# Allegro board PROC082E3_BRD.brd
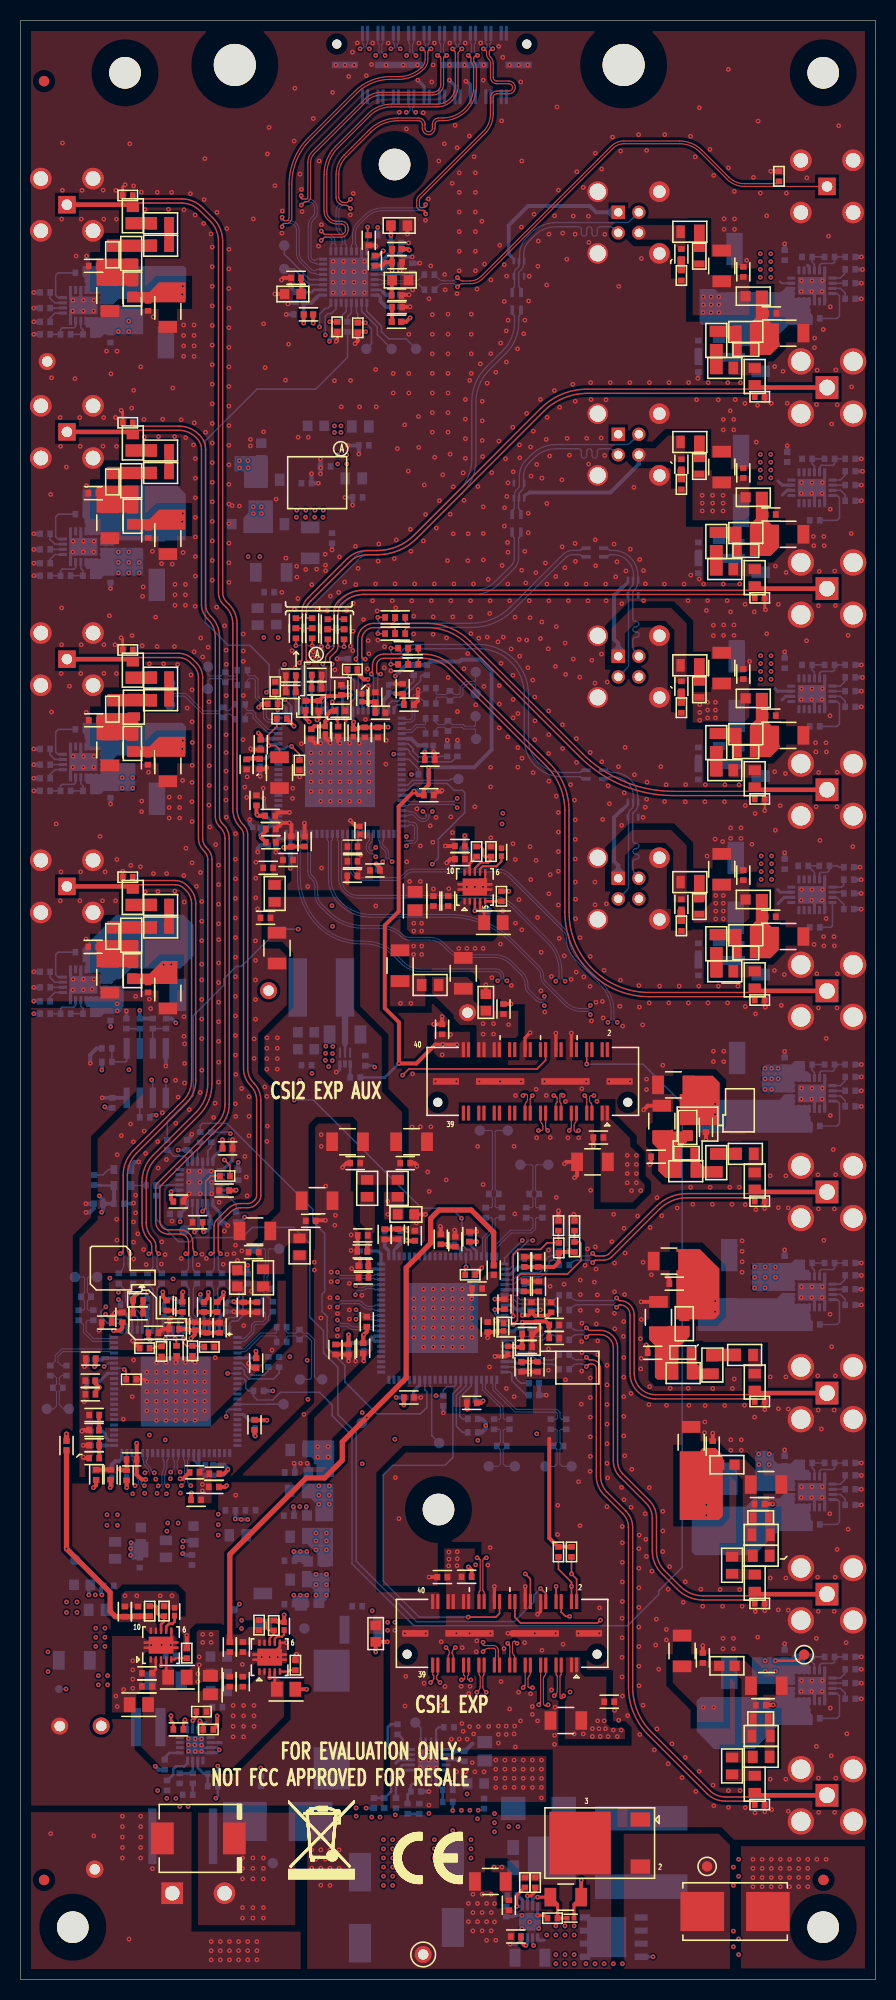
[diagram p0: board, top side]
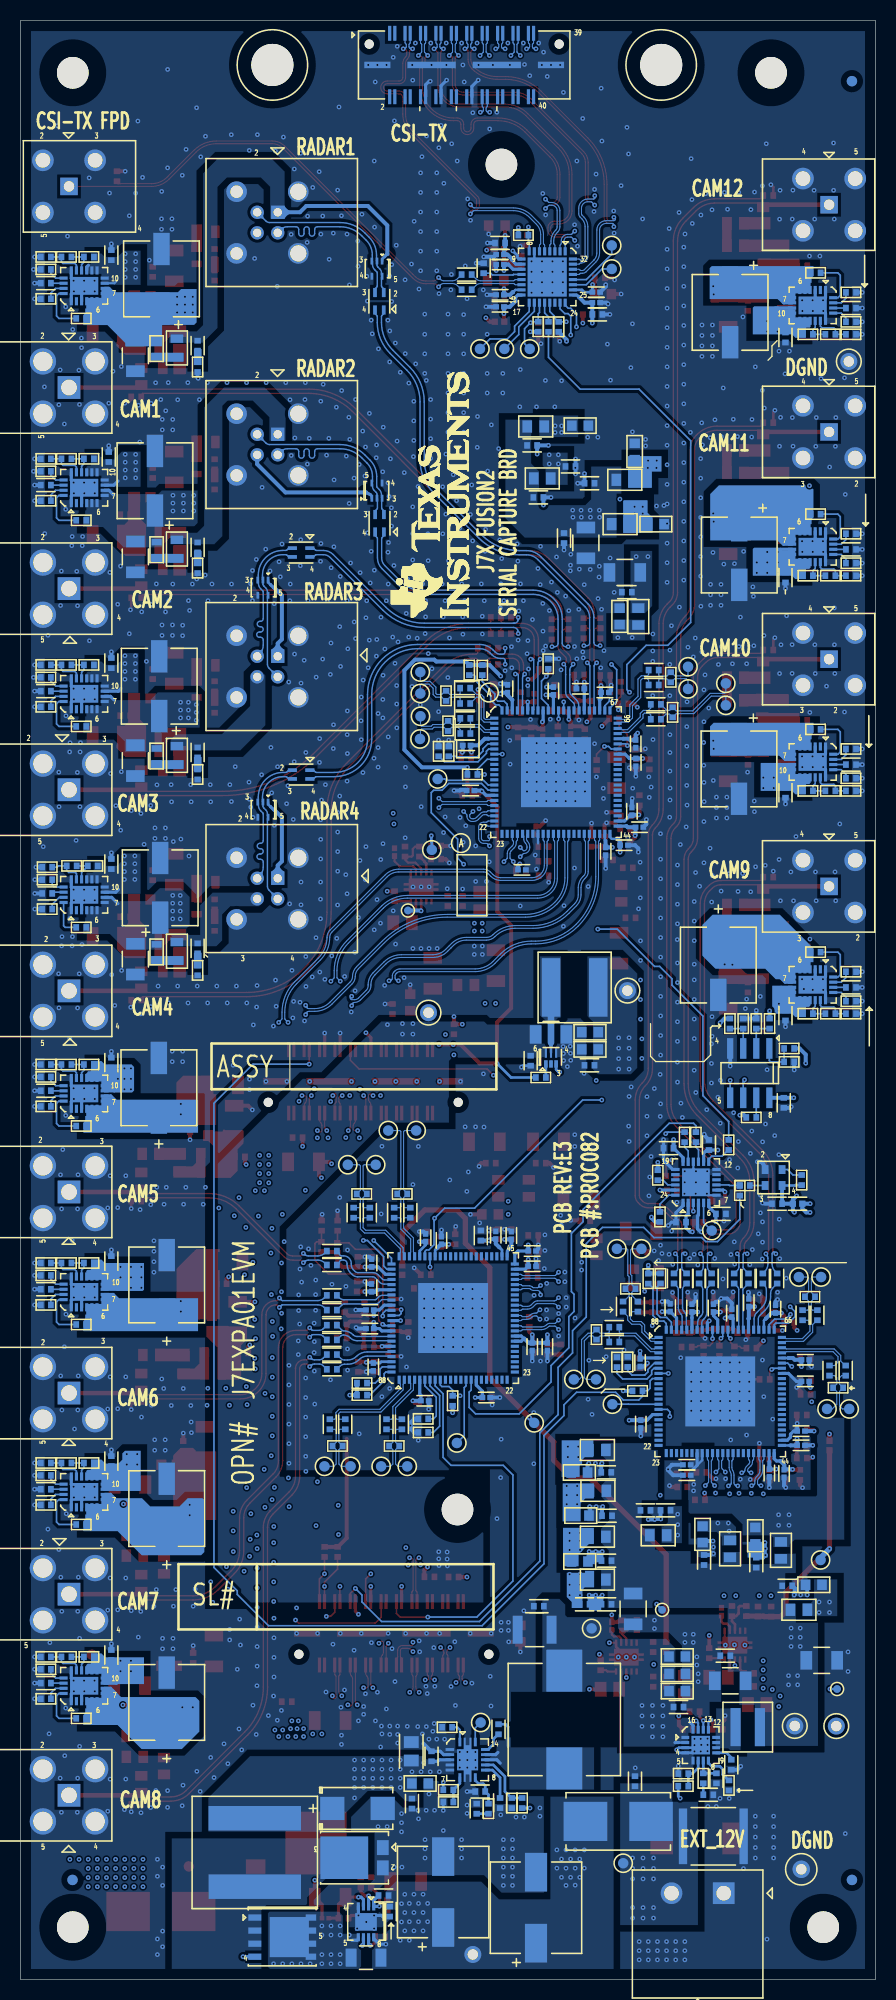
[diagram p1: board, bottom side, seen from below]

Outline 83.16 x 190.5 mm; copper layers: TOP, L02_GND1, L03_SIG1, L04_PWR1, L5_GND2, L6_SIG2, L7_GND3, BOTTOM. Coordinates in mm from the lower left corner of the outline.
Outline path: 0,190.5 0,0 83.16,0 83.16,190.5 0,190.5

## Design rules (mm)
net group C_DOUT_: nets C_DOUT_N C_DOUT_P
net group CAM5_RIN0_: nets CAM5_RIN0_N CAM5_RIN0_P
net group CAM6_RIN1_: nets CAM6_RIN1_N CAM6_RIN1_P
net group CAM7_RIN2_: nets CAM7_RIN2_N CAM7_RIN2_P
net group CAM8_RIN3: nets CAM8_RIN3_N CAM8_RIN3_P
net group CAM9_RIN0_: nets CAM9_RIN0_N CAM9_RIN0_P
net group CAM10_RIN1_: nets CAM10_RIN1_N CAM10_RIN1_P
net group CAM11_RIN2_: nets CAM11_RIN2_N CAM11_RIN2_P
net group CAM12_RIN3_: nets CAM12_RIN3_N CAM12_RIN3_P
net group CMLOUT: nets C_HUB1_CMLOUT3N C_HUB1_CMLOUT3P
net group CMLOUT2: nets C_HUB1_CMLOUT2N C_HUB1_CMLOUT2P
net group DOUT_: nets DOUT_N DOUT_P
net group DP1: nets HUB3_CMLOUT1N HUB3_CMLOUT1P
net group DP2: nets HUB3_CMLOUT0N HUB3_CMLOUT0P
net group DP3: nets HUB3_CMLOUT3N HUB3_CMLOUT3P
net group DP4: nets HUB2_CMLOUT0N HUB2_CMLOUT0P
net group DP_C_HUB3_CMLOUT2: nets C_HUB3_CMLOUT2N C_HUB3_CMLOUT2P
net group DP_CMLOUT0: nets C_HUB1_CMLOUT0N C_HUB1_CMLOUT0P
net group DP_CMLOUT1: nets C_HUB1_CMLOUT1N C_HUB1_CMLOUT1P
net group DP_HUB2_CMLOUT1: nets HUB2_CMLOUT1N HUB2_CMLOUT1P
net group DP_HUB2_CMLOUT2: nets HUB2_CMLOUT2N HUB2_CMLOUT2P
net group DP_HUB2_CMLOUT3: nets HUB2_CMLOUT3N HUB2_CMLOUT3P
net group HUB1_CMLOUT0: nets HUB1_CMLOUT0N HUB1_CMLOUT0P
net group HUB1_CMLOUT1: nets HUB1_CMLOUT1N HUB1_CMLOUT1P
net group HUB1_CMLOUT2: nets HUB1_CMLOUT2N HUB1_CMLOUT2P
net group HUB1_CMLOUT3: nets HUB1_CMLOUT3N HUB1_CMLOUT3P
net group HUB1_RIN0_: nets HUB1_RIN0_N HUB1_RIN0_P
net group HUB1_RIN1_: nets HUB1_RIN1_N HUB1_RIN1_P
net group HUB1_RIN2_: nets HUB1_RIN2_N HUB1_RIN2_P
net group HUB1_RIN3_: nets HUB1_RIN3_N HUB1_RIN3_P
net group HUB2_CMLOUT0: nets C_HUB2_CMLOUT0N C_HUB2_CMLOUT0P
net group HUB2_CMLOUT1: nets C_HUB2_CMLOUT1N C_HUB2_CMLOUT1P
net group HUB2_CMLOUT2: nets C_HUB2_CMLOUT2N C_HUB2_CMLOUT2P
net group HUB2_CMLOUT3: nets C_HUB2_CMLOUT3N C_HUB2_CMLOUT3P
net group HUB3_CMLOUT0: nets C_HUB3_CMLOUT0N C_HUB3_CMLOUT0P
net group HUB3_CMLOUT1: nets C_HUB3_CMLOUT1N C_HUB3_CMLOUT1P
net group HUB3_CMLOUT2: nets HUB3_CMLOUT2N HUB3_CMLOUT2P
net group HUB3_CMLOUT3: nets C_HUB3_CMLOUT3N C_HUB3_CMLOUT3P
net group RDR1_RIN_: nets RDR1_RIN_N RDR1_RIN_P
net group RDR2_RIN_: nets RDR2_RIN_N RDR2_RIN_P
net group RDR3_RIN_: nets RDR3_RIN_N RDR3_RIN_P
net group RDR4_RIN_: nets RDR4_RIN_N RDR4_RIN_P
net group T_RDR1_RIN_: nets T_RDR1_RIN_N T_RDR1_RIN_P
net group T_RDR2_RIN_: nets T_RDR2_RIN_N T_RDR2_RIN_P
net group T_RDR3_RIN_: nets T_RDR3_RIN_N T_RDR3_RIN_P
net group T_RDR4_RIN_: nets T_RDR4_RIN_N T_RDR4_RIN_P
net group C_CAM5_RIN0: nets C_CAM5_RIN0_N
net group C_CAM6_RIN1: nets C_CAM6_RIN1_N
net group C_CAM7_RIN2: nets C_CAM7_RIN2_N
net group C_CAM8_RIN3: nets C_CAM8_RIN3_N
net group C_CAM9_RIN0: nets C_CAM9_RIN0_N
net group C_CAM10_RIN1: nets C_CAM10_RIN1_N
net group C_CAM11_RIN2: nets C_CAM11_RIN2_N
net group C_CAM12_RIN3: nets C_CAM12_RIN3_N
net group CAM1_RIN: nets CAM1_RIN_N
net group CAM2_RIN: nets CAM2_RIN_N
net group CAM3_RIN: nets CAM3_RIN_N
net group CAM4_RIN: nets CAM4_RIN_N
net group CSI: nets CSI_TX_CLK_N CSI_TX_CLK_P CSI_TX_D0_N CSI_TX_D0_P CSI_TX_D1_N CSI_TX_D1_P CSI_TX_D2_N CSI_TX_D2_P CSI_TX_D3_N CSI_TX_D3_P
net group CSI0: nets CSI0_CLK_N CSI0_CLK_P CSI0_D0_N CSI0_D0_P CSI0_D1_N CSI0_D1_P CSI0_D2_N CSI0_D2_P CSI0_D3_N CSI0_D3_P
net group CSI2: nets CSI2_CLK_N CSI2_CLK_P CSI2_D0_N CSI2_D0_P CSI2_D1_N CSI2_D1_P CSI2_D2_N CSI2_D2_P CSI2_D3_N CSI2_D3_P
net group CSI2_0: nets CSI2_0_CLK_N CSI2_0_CLK_P CSI2_0_D0_N CSI2_0_D0_P CSI2_0_D1_P CSI2_0_D2_N CSI2_0_D2_P CSI2_0_D3_N CSI2_0_D3_P
net group CSI2_0_D1_: nets CSI2_0_D1_N
net group PWR: nets VCC_1V8_EN VDD1V8_P_HUB2 VDD_1V1_HUB1_PG VDD_1V1_HUB3_PG

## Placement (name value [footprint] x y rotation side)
C1  0.1uF  [CAP0402_0-75]  64.28 167.79 90 top
C2  4.7uF  [CAP1206_2]  8.69 163.76 270 top
C3  0.1uF  [CAP0402_0-75]  7.11 166.65 180 top
C5  4.7uF  [CAP1206_2]  74.66 160.1 0 top
C6  4.7uF  [CAP1206_2]  68.21 166.64 90 top
C7  0.1uF  [CAP0402_0-75]  70.3 166.06 90 top
C8  0.1uF  [CAP0402_0-75]  73.04 162.02 0 top
C9  0.1uF  [CAP0402_0-75]  12.41 162.76 270 top
C10  4.7uF  [CAP1206_2]  14.33 162.21 270 top
C11  0.1uF  [CAP0402_0-75]  64.28 147.35 90 top
C12  4.7uF  [CAP1206_2]  8.69 141.66 270 top
C13  0.1uF  [CAP0402_0-75]  7.09 144.55 180 top
C14  4.7uF  [CAP1206_2]  74.66 140.54 0 top
C16  0.1uF  [CAP0402_0-75]  70.3 146.51 90 top
C17  0.1uF  [CAP0402_0-75]  72.97 142.46 0 top
C18  0.1uF  [CAP0402_0-75]  12.42 140.69 270 top
C19  4.7uF  [CAP1206_2]  14.33 140.12 270 top
C20  4.7uF  [CAP1206_2]  68.21 147.08 90 top
C21  10uF  [CAP1206_1]  71.99 118.53 270 bottom
C22  0.1uF  [CAP0402_0-75]  34.51 124.7 90 top
C23  0.01uF  [CAP0201_0-5]  26.31 125.16 180 bottom
C24  0.1uF  [CAP0402_0-75]  37.17 125.51 90 top
C25  0.1uF  [CAP0402_0-75]  65.94 119.32 90 bottom
C27  0.1uF  [CAP0402_0-75]  64.28 125.76 90 top
C28  0.01uF  [CAP0201_0-5]  29.64 121.49 270 top
C29  0.01uF  [CAP0201_0-5]  32.36 121.24 270 top
C30  0.1uF  [CAP0402_0-75]  30.89 121.35 270 top
C31  10uF  [CAP1206_1]  25.19 117.36 270 top
C32  4.7uF  [CAP1206_2]  8.69 119.56 270 top
C33  0.1uF  [CAP0402_0-75]  7.12 122.46 180 top
C34  4.7uF  [CAP1206_2]  74.66 120.98 0 top
C36  0.1uF  [CAP0402_0-75]  70.3 126.95 90 top
C37  0.1uF  [CAP0402_0-75]  72.97 122.91 0 top
C38  0.1uF  [CAP0402_0-75]  12.39 118.62 270 top
C39  4.7uF  [CAP1206_2]  14.33 118.02 270 top
C40  4.7uF  [CAP1206_2]  68.21 127.52 90 top
C41  1uF  [CAP0402_0-75]  24.09 108.1 180 top
C43  0.1uF  [CAP0402_0-75]  23.83 103.24 180 top
C44  10uF  [CAP1206_1]  24.94 100.29 270 top
C45  0.1uF  [CAP0402_0-75]  64.28 104.55 90 top
C46  22uF  [CAP1206_2]  36.92 98.59 90 top
C47  10uF  [CAP1206_1]  43.06 97.85 90 top
C49  4.7uF  [CAP1206_2]  8.69 97.46 270 top
C50  0.1uF  [CAP0402_0-75]  7.07 100.42 180 top
C51  4.7uF  [CAP1206_2]  68.21 107.96 90 top
C52  0.1uF  [CAP0402_0-75]  72.97 103.35 0 top
C54  0.1uF  [CAP0402_0-75]  70.3 107.39 90 top
C55  4.7uF  [CAP1206_2]  74.66 101.42 0 top
C57  0.1uF  [CAP0402_0-75]  12.4 96.47 270 top
C58  4.7uF  [CAP1206_2]  14.33 95.92 270 top
C59  10uF  [CAP0603_1]  45.26 95.01 90 top
C60  4.7uF  [CAP1206_2]  63.51 86.99 180 top
C61  0.1uF  [CAP0402_0-75]  46.98 94.37 90 top
C62  0.1uF  [CAP0402_0-75]  41 92.4 90 top
C63  4.7uF  [CAP1206_2]  62.38 83.47 90 top
C64  0.1uF  [CAP0402_0-75]  66.67 82.88 270 top
C65  0.1uF  [CAP0402_0-75]  61.82 80.01 180 top
C66  0.1uF  [CAP0402_0-75]  56.21 81.87 180 top
C67  10uF  [CAP1206_1]  31.81 81.46 180 top
C68  10uF  [CAP1206_1]  38.03 81.46 0 top
C69  10uF  [CAP1206_1]  55.64 79.51 180 top
C70  0.1uF  [CAP0402_0-75]  32.55 79.39 180 top
C71  0.1uF  [CAP0402_0-75]  37.42 79.39 0 top
C72  1uF  [CAP0402_0-75]  19.8 76.72 180 top
C73  10uF  [CAP1206_1]  22.8 72.78 180 top
C74  10uF  [CAP1206_1]  28.85 75.73 0 top
C75  100pF  [CAP0402_0-75]  15.35 75.65 0 top
C76  4.7uF  [CAP1206_2]  63.08 69.86 180 top
C77  0.1uF  [CAP0402_0-75]  22.67 70.73 180 top
C78  10uF  [CAP0603_1]  37.49 74.4 0 top
C79  0.1uF  [CAP0402_0-75]  28.23 73.77 0 top
C81  0.1uF  [CAP0402_0-75]  63.6 67.66 180 top
C82  1uF  [CAP0402_0-75]  35.42 72.46 90 top
C83  0.1uF  [CAP0402_0-75]  33.23 70.8 180 top
C84  10uF  [CAP0603_1]  21.09 68.19 90 top
C85  0.01uF  [CAP0201_0-5]  33.4 70.84 180 bottom
C86  1uF  [CAP0402_0-75]  49.01 69.78 90 top
C87  4.7uF  [CAP1206_2]  62.05 64.4 90 top
C89  0.01uF  [CAP0201_0-5]  8.89 49.2 270 bottom
C91  0.1uF  [CAP0402_0-75]  8.76 49.09 270 top
C92  0.1uF  [CAP0402_0-75]  61.49 60.93 180 top
C93  0.1uF  [CAP0402_0-75]  47.07 65.67 90 top
C94  0.1uF  [CAP0402_0-75]  21.71 65.36 90 top
C95  1uF  [CAP0402_0-75]  19.13 65.4 90 top
C96  0.1uF  [CAP0402_0-75]  49.7 65.37 90 top
C97  0.01uF  [CAP0201_0-5]  12.32 65.81 90 bottom
C98  1uF  [CAP0402_0-75]  8.38 63.88 180 top
C99  0.01uF  [CAP0201_0-5]  16.96 63.52 270 top
C101  0.01uF  [CAP0201_0-5]  13.97 64.8 90 bottom
C102  0.01uF  [CAP0201_0-5]  31.91 61.53 270 bottom
C103  0.01uF  [CAP0201_0-5]  47.4 61.19 270 top
C104  0.1uF  [CAP0402_0-75]  15.18 61.14 270 top
C106  1uF  [CAP0402_0-75]  37.78 56.59 180 top
C107  4.7uF  [CAP1206_2]  65.24 52.24 90 top
C108  0.1uF  [CAP0402_0-75]  67.33 51.87 90 top
C109  1uF  [CAP0402_0-75]  7.36 49.07 270 top
C110  0.01uF  [CAP0201_0-5]  6.82 58.16 180 bottom
C111  4.7uF  [CAP1206_2]  72.52 48.13 0 top
C112  0.1uF  [CAP0402_0-75]  71.88 46.23 0 top
C113  0.1uF  [CAP0402_0-75]  43.39 39.16 0 top
C114  0.1uF  [CAP0402_0-75]  41.03 39.13 180 top
C115  10uF  [CAP0603_1]  34.54 33.63 270 top
C116  4.7uF  [CAP1206_2]  64.35 31.94 90 top
C117  0.1uF  [CAP0402_0-75]  66.37 31.27 90 top
C118  0.1uF  [CAP0402_0-75]  57.26 27.01 0 top
C119  10uF  [CAP1206_1]  53.05 25.18 180 top
C120  4.7uF  [CAP1206_2]  72.55 28.57 0 top
C121  0.1uF  [CAP0402_0-75]  72.01 26.67 0 top
C122  10uF  [CAP1206_1]  71.99 157.9 270 bottom
C123  0.1uF  [CAP0402_0-75]  65.94 158.88 90 bottom
C125  0.1uF  [CAP0402_0-75]  28.36 130.91 270 top
C126  0.1uF  [CAP0402_0-75]  26.78 130.91 270 top
C132  0.047uF  [CAP0402_0-75]  28.36 131.89 270 top
C133  0.1uF  [CAP0402_0-75]  26.78 131.89 270 top
C135  0.1uF  [CAP0402_0-75]  74.33 167.69 90 bottom
C136  1000pF  [CAP0402_0-75]  2.38 162.54 180 bottom
C137  100uF_50V  [CAPAE_D8CASE_8]  14.14 162.12 270 bottom
C138  100uF_50V  [CAPAE_D8CASE_8]  69.45 165.38 90 bottom
C139  1000pF  [CAP0402_0-75]  80.7 164.96 0 bottom
C140  0.1uF  [CAP0402_0-75]  8.75 159.68 270 bottom
C141  0.1uF  [CAP0402_0-75]  24.34 111.87 0 top
C142  10uF  [CAP1206_1]  71.99 138.34 270 bottom
C143  0.1uF  [CAP0402_0-75]  65.94 139.26 90 bottom
C144  0.1uF  [CAP0402_0-75]  33.4 149.19 180 bottom
C145  0.1uF  [CAP0402_0-75]  23.37 120.08 270 top
C146  0.1uF  [CAP0402_0-75]  32.29 110.17 180 top
C147  0.1uF  [CAP0402_0-75]  27.81 145.5 0 bottom
C148  0.1uF  [CAP0402_0-75]  32.79 144.13 180 bottom
C149  1uF  [CAP0402_0-75]  28.81 126.87 0 top
C151  0.1uF  [CAP0402_0-75]  31.47 130.81 270 top
C152  0.1uF  [CAP0402_0-75]  30.29 140.17 270 bottom
C154  0.1uF  [CAP0402_0-75]  29.89 130.81 270 top
C156  10uF  [CAP1206_1]  28.17 139.7 270 bottom
C160  0.047uF  [CAP0402_0-75]  31.47 131.79 270 top
C161  0.1uF  [CAP0402_0-75]  29.89 131.79 270 top
C163  0.1uF  [CAP0402_0-75]  74.58 148.06 90 bottom
C164  1000pF  [CAP0402_0-75]  2.38 139.07 180 bottom
C166  0.1uF  [CAP0402_0-75]  21.57 127.33 0 bottom
C167  0.1uF  [CAP0402_0-75]  21.57 125.89 0 bottom
C168  100uF_50V  [CAPAE_D8CASE_8]  13.25 138.52 270 bottom
C169  100uF_50V  [CAPAE_D8CASE_8]  70.08 145.75 90 bottom
C170  1000pF  [CAP0402_0-75]  80.7 145.33 0 bottom
C171  0.1uF  [CAP0402_0-75]  39.91 125.58 180 bottom
C172  0.01uF  [CAP0201_0-5]  33.21 124.65 90 top
C173  0.01uF  [CAP0201_0-5]  35.79 125.51 90 bottom
C174  0.01uF  [CAP0201_0-5]  28.7 125.52 0 bottom
C175  1uF  [CAP0402_0-75]  34.76 121.27 270 top
C176  0.1uF  [CAP0402_0-75]  8.75 136.34 270 bottom
C177  0.01uF  [CAP0201_0-5]  22.96 112.05 180 bottom
C178  0.1uF  [CAP0402_0-75]  39.91 124.08 180 bottom
C179  0.1uF  [CAP0402_0-75]  21.36 124 0 bottom
C180  0.1uF  [CAP0402_0-75]  39.89 122.64 180 bottom
C181  0.1uF  [CAP0402_0-75]  21.36 122.56 0 bottom
C182  0.1uF  [CAP0402_0-75]  39.89 121.17 180 bottom
C183  0.01uF  [CAP0201_0-5]  23.32 120.16 270 bottom
C184  1uF  [CAP0402_0-75]  29.66 147.14 180 bottom
C185  0.01uF  [CAP0201_0-5]  39.77 120.02 0 bottom
C186  0.01uF  [CAP0201_0-5]  23.31 118.36 270 bottom
C187  0.01uF  [CAP0201_0-5]  33.03 111.75 90 top
C189  0.1uF  [CAP0402_0-75]  35.95 130.88 180 top
C190  0.1uF  [CAP0402_0-75]  35.95 132.46 180 top
C191  0.01uF  [CAP0201_0-5]  39.39 115.62 0 bottom
C195  1uF  [CAP0402_0-75]  39.71 115.17 0 top
C196  0.01uF  [CAP0201_0-5]  23.69 113.59 90 bottom
C198  0.047uF  [CAP0402_0-75]  36.93 130.88 180 top
C201  0.1uF  [CAP0402_0-75]  36.93 132.46 180 top
C203  1uF  [CAP0402_0-75]  24.35 110.59 0 top
C204  0.01uF  [CAP0201_0-5]  34.39 107.91 0 bottom
C205  0.01uF  [CAP0201_0-5]  26.24 109.71 270 bottom
C206  0.01uF  [CAP0201_0-5]  24.46 110.3 180 bottom
C207  0.1uF  [CAP0402_0-75]  26.02 108.87 0 top
C208  1uF  [CAP0402_0-75]  32.28 107.33 180 top
C209  0.1uF  [CAP0402_0-75]  74.33 128.02 90 bottom
C210  1000pF  [CAP0402_0-75]  2.38 118.14 180 bottom
C211  100uF_50V  [CAPAE_D8CASE_8]  13.27 117.72 270 bottom
C212  100uF_50V  [CAPAE_D8CASE_8]  69.67 125.77 90 bottom
C213  1000pF  [CAP0402_0-75]  80.7 125.29 0 bottom
C214  0.1uF  [CAP0402_0-75]  8.75 115.41 270 bottom
C215  10uF  [CAP1206_1]  71.99 99.23 270 bottom
C216  0.1uF  [CAP0402_0-75]  65.94 100.27 90 bottom
C218  0.1uF  [CAP0402_0-75]  37.22 127.89 180 top
C219  0.1uF  [CAP0402_0-75]  37.22 129.47 180 top
C223  0.047uF  [CAP0402_0-75]  38.2 127.89 180 top
C224  100uF_50V  [CAPAE_D8CASE_8]  15.29 98.65 270 bottom
C225  0.1uF  [CAP0402_0-75]  74.33 108.47 90 bottom
C226  0.1uF  [CAP0402_0-75]  38.2 129.47 180 top
C228  0.1uF  [CAP0402_0-75]  74.33 89.16 90 bottom
C229  100uF_50V  [CAPAE_D8CASE_8]  69.58 106.16 90 bottom
C230  1000pF  [CAP0402_0-75]  80.57 105.61 0 bottom
C231  1000pF  [CAP0402_0-75]  2.38 96.47 180 bottom
C232  100uF_50V  [CAPAE_D8CASE_8]  69.7 86.72 90 bottom
C233  1000pF  [CAP0402_0-75]  80.7 86.43 0 bottom
C234  0.1uF  [CAP0402_0-75]  8.75 93.74 270 bottom
C235  10uF  [CAP0603_1]  27.77 92.11 0 bottom
C236  0.1uF  [CAP0402_0-75]  27.82 88.9 0 bottom
C238  0.1uF  [CAP0402_0-75]  24.18 134.91 0 bottom
C239  10uF  [CAP1206_1]  24.38 136.83 0 bottom
C240  10uF  [CAP0603_1]  24.89 132.56 90 bottom
C241  0.1uF  [CAP0402_0-75]  8.92 85.25 270 bottom
C242  100pF  [CAP0402_0-75]  16.19 81.15 90 bottom
C243  100pF  [CAP0402_0-75]  15.03 74.45 180 bottom
C244  0.1uF  [CAP0402_0-75]  74.33 69.85 90 bottom
C245  0.1uF  [CAP0402_0-75]  9.57 75.44 0 bottom
C246  0.1uF  [CAP0402_0-75]  50.76 74.56 270 bottom
C247  0.1uF  [CAP0402_0-75]  49.18 74.56 270 bottom
C248  0.1uF  [CAP0402_0-75]  46.82 74.56 270 bottom
C249  0.1uF  [CAP0402_0-75]  45.24 74.56 270 bottom
C250  100uF_50V  [CAPAE_D8CASE_8]  68.94 67.54 90 bottom
C251  1uF  [CAP0402_0-75]  20.14 80.82 0 top
C252  100pF  [CAP0402_0-75]  20.12 80.84 0 bottom
C253  1000pF  [CAP0402_0-75]  80.7 67.12 0 bottom
C254  0.01uF  [CAP0201_0-5]  43.76 72.13 90 bottom
C255  1uF  [CAP0402_0-75]  31.9 61.26 270 top
C256  0.01uF  [CAP0201_0-5]  36.93 72.38 90 bottom
C257  0.01uF  [CAP0201_0-5]  35.42 72.35 90 bottom
C258  1uF  [CAP0402_0-75]  33.29 72.36 180 top
C260  0.1uF  [CAP0402_0-75]  52.88 70.84 180 bottom
C261  0.01uF  [CAP0201_0-5]  49.01 69.67 90 bottom
C262  0.047uF  [CAP0402_0-75]  52.88 69.48 180 bottom
C263  0.01uF  [CAP0201_0-5]  33.4 69.35 180 bottom
C264  0.047uF  [CAP0402_0-75]  19.59 68.17 270 bottom
C265  0.1uF  [CAP0402_0-75]  18.37 68.17 270 bottom
C266  0.047uF  [CAP0402_0-75]  17.15 68.17 270 bottom
C267  0.1uF  [CAP0402_0-75]  15.93 68.17 270 bottom
C268  0.047uF  [CAP0402_0-75]  13.74 68.17 270 bottom
C269  0.1uF  [CAP0402_0-75]  12.35 68.17 270 bottom
C270  0.047uF  [CAP0402_0-75]  10.95 68.17 270 bottom
C271  0.1uF  [CAP0402_0-75]  9.56 68.17 270 bottom
C272  1uF  [CAP0402_0-75]  48.97 67.41 90 top
C273  0.01uF  [CAP0201_0-5]  49.01 67.26 90 bottom
C274  0.1uF  [CAP0402_0-75]  52.88 66.53 180 bottom
C275  0.01uF  [CAP0201_0-5]  19.96 65.33 90 bottom
C276  0.1uF  [CAP0402_0-75]  24.55 65.43 270 bottom
C277  0.1uF  [CAP0402_0-75]  23.11 65.43 270 bottom
C278  0.01uF  [CAP0201_0-5]  17.85 65.29 90 bottom
C279  0.01uF  [CAP0201_0-5]  7.24 51.94 180 bottom
C280  0.01uF  [CAP0201_0-5]  49.18 65.11 0 bottom
C281  0.047uF  [CAP0402_0-75]  52.88 65.1 180 bottom
C282  0.01uF  [CAP0201_0-5]  9.72 65.19 90 bottom
C283  0.1uF  [CAP0402_0-75]  7.09 64.6 270 bottom
C284  0.1uF  [CAP0402_0-75]  5.65 64.6 270 bottom
C285  0.1uF  [CAP0402_0-75]  52.88 63.63 180 bottom
C286  0.1uF  [CAP0402_0-75]  25.4 63.44 180 bottom
C287  0.01uF  [CAP0201_0-5]  49.18 63.3 0 bottom
C288  0.047uF  [CAP0402_0-75]  52.88 62.2 180 bottom
C289  0.1uF  [CAP0402_0-75]  25.4 61.99 180 bottom
C290  0.01uF  [CAP0201_0-5]  33.38 61.53 270 bottom
C291  0.01uF  [CAP0201_0-5]  42.22 71.87 90 bottom
C292  0.1uF  [CAP0402_0-75]  52.88 60.77 180 bottom
C293  0.01uF  [CAP0201_0-5]  6.82 60.27 180 bottom
C294  1uF  [CAP0402_0-75]  20.42 45.62 0 bottom
C295  0.01uF  [CAP0201_0-5]  22.9 59.98 270 bottom
C296  0.01uF  [CAP0201_0-5]  48.84 59.56 270 bottom
C297  0.047uF  [CAP0402_0-75]  52.88 59.34 180 bottom
C298  0.1uF  [CAP0402_0-75]  4.47 59.21 90 bottom
C299  0.1uF  [CAP0402_0-75]  2.89 59.21 90 bottom
C300  1uF  [CAP0402_0-75]  6.79 56.9 180 top
C301  0.01uF  [CAP0201_0-5]  43.84 56.27 180 bottom
C302  0.01uF  [CAP0201_0-5]  37.85 56.59 180 bottom
C303  0.1uF  [CAP0402_0-75]  74.33 50.4 90 bottom
C304  1uF  [CAP0402_0-75]  28.29 36.48 180 bottom
C305  0.1uF  [CAP0402_0-75]  53.07 53.99 90 bottom
C306  0.1uF  [CAP0402_0-75]  51.58 53.99 90 bottom
C307  0.1uF  [CAP0402_0-75]  47.56 53.99 90 bottom
C308  0.1uF  [CAP0402_0-75]  46.06 53.99 90 bottom
C309  1uF  [CAP0402_0-75]  22.76 53.94 270 top
C310  0.01uF  [CAP0201_0-5]  22.83 54.01 270 bottom
C311  0.01uF  [CAP0201_0-5]  7.24 53.33 180 bottom
C312  1000pF  [CAP0402_0-75]  80.7 47.67 0 bottom
C313  1uF  [CAP0402_0-75]  7.16 50.7 180 top
C314  100uF_50V  [CAPAE_D8CASE_8]  68.94 45.79 90 bottom
C316  0.01uF  [CAP0201_0-5]  18.35 50.05 0 bottom
C317  0.1uF  [CAP0402_0-75]  36.7 72.47 90 top
C318  0.1uF  [CAP0402_0-75]  26.19 49.31 0 bottom
C319  0.01uF  [CAP0201_0-5]  10.32 49.25 270 bottom
C321  0.01uF  [CAP0201_0-5]  18.35 49.03 0 bottom
C322  0.1uF  [CAP0402_0-75]  33.32 61.38 270 top
C323  0.1uF  [CAP0402_0-75]  26.11 45.09 0 bottom
C324  0.1uF  [CAP0402_0-75]  17.85 65.4 90 top
C325  0.1uF  [CAP0402_0-75]  6.78 58.23 180 top
C326  0.1uF  [CAP0402_0-75]  50.42 67.4 90 top
C327  0.1uF  [CAP0402_0-75]  26.16 40.72 0 bottom
C328  0.1uF  [CAP0402_0-75]  16.67 40.79 90 bottom
C329  0.1uF  [CAP0402_0-75]  11.59 40.54 90 bottom
C330  0.1uF  [CAP0402_0-75]  8.58 38.28 180 bottom
C331  0.1uF  [CAP0402_0-75]  7.16 51.94 180 top
C332  0.1uF  [CAP0402_0-75]  43.66 72.24 90 top
C333  0.1uF  [CAP0402_0-75]  26.16 36.48 0 bottom
C334  10uF  [CAP1206_1]  23.57 36.03 270 bottom
C335  0.1uF  [CAP0402_0-75]  32.74 36.3 0 bottom
C336  0.1uF  [CAP0402_0-75]  74.33 31.55 90 bottom
C338  0.1uF  [CAP0402_0-75]  36.67 24.33 90 bottom
C339  1000pF  [CAP0402_0-75]  80.7 28.82 0 bottom
C340  100uF_50V  [CAPAE_D8CASE_8]  68.94 26.94 90 bottom
C341  4.7uF  [CAP0805_1-5]  45.15 22.19 90 bottom
C342  0.1uF  [CAP0402_0-75]  22.92 59.94 270 top
C343  0.1uF  [CAP0402_0-75]  22.37 45.62 180 bottom
C344  0.1uF  [CAP0402_0-75]  43.18 21.7 90 bottom
C345  91pF  [CAP0402_0-75]  38.45 18.27 0 bottom
C346  10uF  [CAP1206_1]  5.23 31.03 180 bottom
C347  10uF  [CAP0603_1]  44.29 19.06 180 bottom
C348  0.012uF  [CAP0402_0-75]  38.79 16.6 90 bottom
C350  2700pF  [CAP0402_0-75]  36.52 17.15 270 bottom
C351  0.1uF  [CAP0402_0-75]  47.5 7.21 90 top
C352  0.1uF  [CAP0402_0-75]  23.39 19.27 270 bottom
C353  22uF  [CAP2220_5-5]  15.77 13.92 180 bottom
C354  1uF  [CAP0402_0-75]  40.16 104.88 90 top
C355  4.7uF  [CAP0805_1-5]  46 102.77 0 top
C356  10uF  [CAP0402_0-75]  42.74 110.23 180 top
C357  1uF  [CAP0402_0-75]  20.35 28.96 90 top
C358  4.7uF  [CAP0805_1-5]  25.83 28.22 0 top
C359  10uF  [CAP0402_0-75]  21.63 32.32 270 top
C360  1uF  [CAP0402_0-75]  12.29 28.5 180 top
C361  4.7uF  [CAP0805_1-5]  15.26 29.39 0 top
C362  10uF  [CAP0402_0-75]  11.42 35.77 90 top
C363  0.01uF  [CAP0201_0-5]  46.78 109.63 90 top
C364  0.01uF  [CAP0201_0-5]  25.65 34.37 90 top
C365  0.01uF  [CAP0201_0-5]  14.98 35.76 90 top
C366  0.1uF  [CAP0402_0-75]  45.44 63.44 270 top
C367  1uF  [CAP0402_0-75]  44.41 67.2 180 top
C368  0.01uF  [CAP0201_0-5]  46.99 63.45 270 top
C369  0.1uF  [CAP0402_0-75]  31.2 125.41 90 top
C370  0.01uF  [CAP0201_0-5]  31.32 125.3 90 bottom
C371  1uF  [CAP0402_0-75]  29.02 123.86 270 top
C372  0.1uF  [CAP0402_0-75]  15.74 65.41 90 top
C373  0.01uF  [CAP0201_0-5]  15.76 65.29 90 bottom
C374  1uF  [CAP0402_0-75]  14.21 65.54 90 top
C381  0.01uF  [CAP0201_0-5]  36.52 163.83 0 bottom
C382  1uF  [CAP0402_0-75]  36.58 163.77 0 top
C383  0.01uF  [CAP0201_0-5]  36.52 166.78 0 bottom
C384  1uF  [CAP0402_0-75]  36.63 167 0 top
C385  1uF  [CAP0402_0-75]  36.52 168.87 0 bottom
C386  0.01uF  [CAP0201_0-5]  36.52 167.75 0 bottom
C387  1uF  [CAP0402_0-75]  36.62 162.64 0 top
C390  1uF  [CAP0402_0-75]  26.8 165.48 180 top
C392  1uF  [CAP0402_0-75]  27.05 161.93 180 bottom
C398  0.01uF  [CAP0201_0-5]  36.52 162.66 0 bottom
C399  0.01uF  [CAP0201_0-5]  27.16 164.08 180 bottom
C400  0.01uF  [CAP0201_0-5]  27.16 163.07 180 bottom
C405  0.1uF  [CAP0402_0-75]  39.77 164.32 180 bottom
C406  0.047uF  [CAP0402_0-75]  39.77 165.8 180 bottom
C407  0.1uF  [CAP0402_0-75]  38.11 166.42 90 bottom
C408  0.022uF  [CAP0402_0-75]  34.47 167.16 270 top
C409  1uF  [CAP0402_0-75]  33.87 169.13 270 top
C410  10uF  [CAP0603_1]  6 38.38 0 bottom
C411  0.1uF  [CAP0402_0-75]  6.82 60.38 180 top
C412  10uF  [CAP0603_1]  11.68 43.15 270 bottom
C413  1uF  [CAP0402_0-75]  7.16 54.89 180 top
C414  1uF  [CAP0402_0-75]  18.85 49.18 0 top
C415  1uF  [CAP0402_0-75]  16.93 49.32 180 top
C416  1uF  [CAP0402_0-75]  10.8 50.57 0 top
C417  0.1uF  [CAP0402_0-75]  17.07 46.64 180 top
C418  0.1uF  [CAP0402_0-75]  18.8 47.89 0 top
C419  0.1uF  [CAP0402_0-75]  10.31 49.02 270 top
C420  0.1uF  [CAP0402_0-75]  7.14 53.44 180 top
C421  0.1uF  [CAP0402_0-75]  11.44 66.05 180 top
C422  1uF  [CAP0402_0-75]  11.44 64.78 180 top
C423  10uF  [CAP0603_1]  16.81 43.28 270 bottom
C424  0.1uF  [CAP0402_0-75]  18.1 63.38 270 top
C425  0.1uF  [CAP0402_0-75]  9.91 64.39 270 top
C426  0.1uF  [CAP0402_0-75]  14.94 63.25 0 top
C427  1uF  [CAP0402_0-75]  12.93 62.89 180 top
C428  1uF  [CAP0402_0-75]  22.99 65.36 90 top
C429  1uF  [CAP0402_0-75]  19.37 63.38 270 top
C430  10uF  [CAP0603_1]  28.8 49.3 180 bottom
C431  0.1uF  [CAP0402_0-75]  33.35 69.41 180 top
C432  0.1uF  [CAP0402_0-75]  38.39 72.35 90 bottom
C433  0.1uF  [CAP0402_0-75]  40.88 71.98 90 top
C434  0.1uF  [CAP0402_0-75]  33.68 63.96 90 top
C435  1uF  [CAP0402_0-75]  33.36 68.26 180 top
C436  1uF  [CAP0402_0-75]  38.35 72.32 90 top
C437  1uF  [CAP0402_0-75]  42.29 71.75 90 top
C438  1uF  [CAP0402_0-75]  30.63 61.26 270 top
C439  10uF  [CAP0603_1]  28.66 45.11 180 bottom
C440  0.1uF  [CAP0402_0-75]  43.89 56.07 180 top
C441  0.1uF  [CAP0402_0-75]  49.28 61.51 0 top
C442  1uF  [CAP0402_0-75]  49.28 62.78 0 top
C443  10uF  [CAP0603_1]  28.77 40.64 180 bottom
C444  0.1uF  [CAP0402_0-75]  51.92 63.65 0 top
C445  0.1uF  [CAP0402_0-75]  48.73 59.58 270 top
C446  0.1uF  [CAP0402_0-75]  50.36 69.78 90 top
C447  1uF  [CAP0402_0-75]  50.29 59.58 270 top
C448  1uF  [CAP0402_0-75]  51.61 65.37 90 top
C449  1uF  [CAP0402_0-75]  51.92 62.38 0 top
C450  0.1uF  [CAP0402_0-75]  26.28 125.21 180 top
C451  0.1uF  [CAP0402_0-75]  31.07 123.38 0 top
C452  0.1uF  [CAP0402_0-75]  33.49 121.28 270 top
C453  1uF  [CAP0402_0-75]  28.28 121.1 270 top
C454  1uF  [CAP0402_0-75]  26.29 126.81 180 top
C455  1uF  [CAP0402_0-75]  37.78 123.97 0 top
C456  0.1uF  [CAP0402_0-75]  28.8 125.55 0 top
C457  1uF  [CAP0402_0-75]  35.01 123.19 0 top
C458  10uF  [CAP0603_1]  21.36 141.53 180 bottom
C459  0.1uF  [CAP0402_0-75]  24.28 113.15 0 top
C460  0.1uF  [CAP0402_0-75]  26.35 110.67 90 top
C461  0.1uF  [CAP0402_0-75]  32.29 108.74 180 top
C462  0.1uF  [CAP0402_0-75]  23.26 118.18 270 top
C463  1uF  [CAP0402_0-75]  21.99 118.16 270 top
C464  1uF  [CAP0402_0-75]  34.48 107.85 0 top
C465  1uF  [CAP0402_0-75]  27.63 110.67 90 top
C466  1uF  [CAP0402_0-75]  22.95 114.66 90 top
C467  10uF  [CAP0603_1]  23.42 148.59 90 bottom
C468  10uF  [CAP0603_1]  28.73 151.1 180 bottom
C469  0.1uF  [CAP0402_0-75]  39.82 118.62 0 top
C470  10uF  [CAP0603_1]  26.49 163.91 180 top
C471  10uF  [CAP0603_1]  36.94 165.25 0 top
C472  10uF  [CAP0603_1]  36.83 170.57 0 top
C473  1uF  [CAP0402_0-75]  17.22 73.63 180 top
C474  100pF  [CAP0402_0-75]  18.91 73.64 0 bottom
C484  0.1uF  [CAP0402_0-75]  15.35 24.32 180 top
C485  0.1uF  [CAP0402_0-75]  19.15 26.49 180 bottom
C491  10uF  [CAP0603_1]  19.28 31.41 180 bottom
C492  10uF  [CAP0603_1]  19.28 28.04 180 bottom
C493  10uF  [CAP0603_1]  19.28 29.72 180 bottom
C495  100uF  [CAP1206_2]  14.12 29.04 0 bottom
C496  0.1uF  [CAP0402_0-75]  14.61 31.48 0 bottom
C500  2700pF  [CAP0402_0-75]  14.02 20.88 270 bottom
C501  3900pF  [CAP0402_0-75]  16.26 17.96 180 bottom
C502  82pF  [CAP0402_0-75]  15.47 19.56 270 bottom
C507  47uF  [CAP1210_2-75]  33.15 34.01 0 bottom
C508  10uF  [CAP0603_1]  27.77 90.45 0 bottom
C509  4.7uF  [CAP1206_2]  31.56 91.9 180 bottom
C510  0.1uF  [CAP0402_0-75]  33.54 89.35 270 bottom
C511  4.7uF  [CAP0805_1-5]  18.47 28.63 90 top
C512  0.1uF  [CAP0402_0-75]  21.62 28.96 90 top
C513  0.1uF  [CAP0402_0-75]  20.36 32.32 270 top
C514  4.7uF  [CAP0805_1-5]  38.38 104.88 90 top
C515  0.1uF  [CAP0402_0-75]  41.61 104.88 90 top
C516  0.1uF  [CAP0402_0-75]  42.74 108.95 180 top
C517  4.7uF  [CAP0805_1-5]  11.51 26.72 180 top
C518  0.1uF  [CAP0402_0-75]  12.29 29.77 180 top
C519  0.1uF  [CAP0402_0-75]  10.15 35.77 90 top
C521  10uF  [CAP1206_2]  45.7 9.53 0 top
C522  0.47uF  [CAP0402_0-75]  48.18 4.18 180 top
C523  1000pF  [CAP0402_0-75]  47.85 8.16 0 bottom
C524  0.1uF  [CAP0402_0-75]  47.25 6.6 90 bottom
C525  82uF_35V  [CAPAE_E12CASE_12]  33.02 6.98 90 bottom
C526  0.02uF  [CAP1206_1]  53.03 8 180 top
C527  0.1uF  [CAP0402_0-75]  45.09 17.1 90 bottom
C528  47uF_20V  [CAPT6032C_3]  50.38 16.63 180 bottom
C529  82uF_35V  [CAPAE_E12CASE_12]  42.05 8.5 90 bottom
D1  V20PW45C-M3/I  [TO-252AE-3_V20PW45C_1-6]  56.34 13.26 90 top
D2  SMCJ24A  [DIO_SMC_2-7]  17.3 13.72 180 top
D3  FSV10150V  [TO277-3_FSV10150V_1-2]  50.67 11.84 0 bottom
F1  10A  [FUSEH_154004_380X200_SMD_3-9]  25.02 15.37 0 bottom
F2  10A  [FUSEH_154004_380X200_SMD_3-9]  69.51 6.6 180 top
FL1  1.5KE  [EMIFIL_BLM18R_0603]  10.92 171.52 90 top
FL2  1.5KE  [EMIFIL_BLM18R_0603]  71.41 155.89 270 top
FL3  1.5KE  [EMIFIL_BLM18R_0603]  13.62 168.6 0 top
FL4  1.5KE  [EMIFIL_BLM18R_0603]  13.62 170.79 180 top
FL5  1.5KE  [EMIFIL_BLM18R_0603]  67.68 159.4 270 top
FL6  1.5KE  [EMIFIL_BLM18R_0603]  68.5 156.72 0 top
FL7  1K  [EMIFIL_BLM18A_0603_1]  10.88 164.39 90 top
FL8  1K  [EMIFIL_BLM18A_0603_1]  71.28 163.7 0 top
FL9  1.5KE  [EMIFIL_BLM18R_0603]  10.92 149.42 90 top
FL10  1.5KE  [EMIFIL_BLM18R_0603]  71.41 136.33 270 top
FL11  1.5KE  [EMIFIL_BLM18R_0603]  13.62 146.5 0 top
FL12  1.5KE  [EMIFIL_BLM18R_0603]  13.62 148.69 180 top
FL13  1.5KE  [EMIFIL_BLM18R_0603]  67.68 139.84 270 top
FL14  1.5KE  [EMIFIL_BLM18R_0603]  68.5 137.16 0 top
FL15  1K  [EMIFIL_BLM18A_0603_1]  10.88 142.3 90 top
FL16  1K  [EMIFIL_BLM18A_0603_1]  71.28 144.14 0 top
FL17  1.5KE  [EMIFIL_BLM18R_0603]  10.92 127.32 90 top
FL18  1.5KE  [EMIFIL_BLM18R_0603]  71.41 116.77 270 top
FL19  1.5KE  [EMIFIL_BLM18R_0603]  13.62 124.4 0 top
FL20  1.5KE  [EMIFIL_BLM18R_0603]  13.62 126.59 180 top
FL21  1.5KE  [EMIFIL_BLM18R_0603]  67.68 120.28 270 top
FL22  1.5KE  [EMIFIL_BLM18R_0603]  68.5 117.6 0 top
FL23  1K  [EMIFIL_BLM18A_0603_1]  10.88 120.2 90 top
FL24  1K  [EMIFIL_BLM18A_0603_1]  71.28 124.58 0 top
FL25  100E  [EMIFIL_BLM18R_0603]  24.72 105.61 90 top
FL26  100E  [EMIFIL_BLM18R_0603]  39.84 96.71 180 top
FL27  1.5KE  [EMIFIL_BLM18R_0603]  10.92 105.23 90 top
FL28  1.5KE  [EMIFIL_BLM18R_0603]  71.41 97.21 270 top
FL29  1.5KE  [EMIFIL_BLM18R_0603]  13.62 102.31 0 top
FL30  1K  [EMIFIL_BLM18A_0603_1]  71.28 105.02 0 top
FL31  1.5KE  [EMIFIL_BLM18R_0603]  13.62 104.5 180 top
FL32  1.5KE  [EMIFIL_BLM18R_0603]  67.68 100.72 270 top
FL33  1.5KE  [EMIFIL_BLM18R_0603]  68.5 98.04 0 top
FL34  1K  [EMIFIL_BLM18A_0603_1]  10.88 98.1 90 top
FL35  1K  [EMIFIL_BLM18A_0603_1]  64.89 82.85 270 top
FL36  1.5KE  [EMIFIL_BLM18R_0603]  70.51 80.29 0 top
FL37  1.5KE  [EMIFIL_BLM18R_0603]  67.68 79.44 90 top
FL38  1.5KE  [EMIFIL_BLM18R_0603]  71.41 77.65 270 top
FL39  100E  [EMIFIL_BLM18R_0603]  33.72 76.93 270 top
FL40  100E  [EMIFIL_BLM18R_0603]  36.69 76.93 270 top
FL41  100E  [EMIFIL_BLM18R_0603]  23.59 68.23 270 top
FL42  100E  [EMIFIL_BLM18R_0603]  27.14 71.24 270 top
FL43  1K  [EMIFIL_BLM18A_0603_1]  64.56 63.78 270 top
FL44  1.5KE  [EMIFIL_BLM18R_0603]  70.43 60.73 0 top
FL45  1.5KE  [EMIFIL_BLM18R_0603]  67.3 59.75 90 top
FL46  1.5KE  [EMIFIL_BLM18R_0603]  71.41 58.1 270 top
FL47  1K  [EMIFIL_BLM18A_0603_1]  68.71 50.06 0 top
FL48  1.5KE  [EMIFIL_BLM18R_0603]  69.21 40.28 270 top
FL49  1.5KE  [EMIFIL_BLM18R_0603]  72.04 41.2 180 top
FL50  1.5KE  [EMIFIL_BLM18R_0603]  71.41 38.54 270 top
FL51  1K  [EMIFIL_BLM18A_0603_1]  68.71 30.5 0 top
FL52  1.5KE  [EMIFIL_BLM18R_0603]  69.21 20.76 270 top
FL53  1.5KE  [EMIFIL_BLM18R_0603]  72.04 21.65 180 top
FL54  1.5KE  [EMIFIL_BLM18R_0603]  71.41 18.98 270 top
FL55  100E  [EMIFIL_BLM18R_0603]  33.05 151.02 180 bottom
FL56  100E  [EMIFIL_BLM18R_0603]  32.41 145.97 180 bottom
FL57  100E  [EMIFIL_BLM18R_0603]  24.38 145.84 180 bottom
FL58  100E  [EMIFIL_BLM18R_0603]  24.84 141.53 180 bottom
FL59  100E  [EMIFIL_BLM18R_0603]  23.06 132.54 270 bottom
FL60  120E  [EMIFIL_BLM15A_0402_0-6]  7.57 75.44 0 bottom
FL61  100E  [EMIFIL_BLM18R_0603]  27.05 51.49 0 bottom
FL62  100E  [EMIFIL_BLM18R_0603]  27 47.52 0 bottom
FL63  100E  [EMIFIL_BLM18R_0603]  27.05 43.06 0 bottom
FL64  100E  [EMIFIL_BLM18R_0603]  14.14 41.88 90 bottom
FL65  100E  [EMIFIL_BLM18R_0603]  9.19 41.73 90 bottom
FL66  100E  [EMIFIL_BLM18R_0603]  27.05 38.88 0 bottom
FL67  100E  [EMIFIL_BLM18R_0603]  7.44 35.95 180 bottom
FL68  100E  [EMIFIL_BLM18R_0603]  21.13 43.19 180 bottom
FL69  120E  [EMIFIL_BLM15A_0402_0-6]  46.02 68.98 270 top
FL70  120E  [EMIFIL_BLM15A_0402_0-6]  27.71 123.89 90 top
FL71  120E  [EMIFIL_BLM15A_0402_0-6]  4.47 51.92 90 top
FL76  1K  [EMIFIL_BLM15A_0402_0-6]  36.57 161.21 0 top
FL78  1K  [EMIFIL_BLM15A_0402_0-6]  28 161.93 0 top
FL80  1K  [EMIFIL_BLM15A_0402_0-6]  36.6 168.28 180 top
J1  CON_PMC_2X20_M  [CON_PMC2X20_QTH-020-01-D-DP-A_P_S_S_4-4]  49.83 87.33 180 top
J2  CON_PMC_2X20_M  [CON_PMC2X20_QTH-020-01-D-DP-A_P_S_S_4-4]  46.84 33.66 180 top
J3  CON_JACK4_D4S10A-400L5  [CON_JACK4_D4S10A-400L5-Z_P_S_T_15-4]  58.14 171.86 270 bottom
J4  CON_JACK5_59S20X-400T5  [CON_JACK5_59S20X-400T5-Z_P_R_T_10-1]  78.45 154.81 270 bottom
J5  CON_JACK5_59S10H-400T5  [CON_JACK5_59S10H-400T5-Z_P_S_T_12-5]  4.51 172.59 90 bottom
J6  CON_JACK4_D4S10A-400L5  [CON_JACK4_D4S10A-400L5-Z_P_S_T_15-4]  58.14 150.27 270 bottom
J7  CON_JACK5_59S20X-400T5  [CON_JACK5_59S20X-400T5-Z_P_R_T_10-1]  78.45 135.25 270 bottom
J8  CON_JACK5_59S10H-400T5  [CON_JACK5_59S10H-400T5-Z_P_S_T_12-5]  4.51 150.5 90 bottom
J9  CON_JACK4_D4S10A-400L5  [CON_JACK4_D4S10A-400L5-Z_P_S_T_15-4]  58.14 128.68 270 bottom
J10  CON_JACK5_59S20X-400T5  [CON_JACK5_59S20X-400T5-Z_P_R_T_10-1]  78.45 115.7 270 bottom
J11  CON_JACK5_59S10H-400T5  [CON_JACK5_59S10H-400T5-Z_P_S_T_12-5]  4.51 128.4 90 bottom
J12  CON_JACK4_D4S10A-400L5  [CON_JACK4_D4S10A-400L5-Z_P_S_T_15-4]  58.14 107.09 270 bottom
J13  CON_JACK5_59S20X-400T5  [CON_JACK5_59S20X-400T5-Z_P_R_T_10-1]  78.45 96.14 270 bottom
J14  CON_JACK5_59S10H-400T5  [CON_JACK5_59S10H-400T5-Z_P_S_T_12-5]  4.51 106.3 90 bottom
J15  CON_JACK5_59S20X-400T5  [CON_JACK5_59S20X-400T5-Z_P_R_T_10-1]  78.45 76.58 270 bottom
J16  CON_JACK5_59S20X-400T5  [CON_JACK5_59S20X-400T5-Z_P_R_T_10-1]  78.45 57.02 270 bottom
J17  CON_JACK5_59S20X-400T5  [CON_JACK5_59S20X-400T5-Z_P_R_T_10-1]  78.45 37.47 270 bottom
J18  CON_JACK5_59S20X-400T5  [CON_JACK5_59S20X-400T5-Z_P_R_T_10-1]  78.45 17.91 270 bottom
J19  CON_TRBLK_1X2  [CON_TB1X2_1757242_P_R_T_8-6]  14.76 8.39 180 bottom
J20  CON_PMC_2X20_M  [CON_PMC2X20_QTH-020-01-D-DP-A_P_S_S_4-4]  40.01 186.18 180 bottom
J21  CON_JACK5_59S10H-400T5  [CON_JACK5_59S10H-400T5-Z_P_S_T_12-5]  78.45 174.37 270 bottom
L1  10uH  [IND_MLZ2012N_90X60_SMD]  65.1 169.96 0 top
L2  10uH  [IND_MLZ2012N_90X60_SMD]  10.77 167.85 90 top
L3  10uH  [IND_MLZ2012N_90X60_SMD]  70.55 160.22 180 top
L4  10uH  [IND_MLZ2012N_90X60_SMD]  65.1 149.51 0 top
L5  10uH  [IND_MLZ2012N_90X60_SMD]  10.77 145.75 90 top
L6  10uH  [IND_MLZ2012N_90X60_SMD]  70.55 140.66 180 top
L7  10uH  [IND_MLZ2012N_90X60_SMD]  67.95 119.04 270 bottom
L8  10uH  [IND_MLZ2012N_90X60_SMD]  65.1 127.8 0 top
L9  10uH  [IND_MLZ2012N_90X60_SMD]  11.02 123.73 90 top
L10  10uH  [IND_MLZ2012N_90X60_SMD]  70.55 121.1 180 top
L11  10uH  [IND_MLZ2012N_90X60_SMD]  65.1 106.72 0 top
L12  10uH  [IND_MLZ2012N_90X60_SMD]  10.77 101.55 90 top
L13  10uH  [IND_MLZ2012N_90X60_SMD]  70.55 101.55 180 top
L14  10uH  [IND_MLZ2012N_90X60_SMD]  64.71 78.6 0 top
L15  10uH  [IND_MLZ2012N_90X60_SMD]  64.45 58.97 0 top
L16  10uH  [IND_MLZ2012N_90X60_SMD]  72.04 43.24 0 top
L17  10uH  [IND_MLZ2012N_90X60_SMD]  72.04 23.68 0 top
L18  10uH  [IND_MLZ2012N_90X60_SMD]  67.95 158.66 270 bottom
L19  90E  [IND4_DLW21H_90X60_SMD_1-4]  48.26 163.2 90 bottom
L20  10uH  [IND_MLZ2012N_90X60_SMD]  67.95 139.11 270 bottom
L21  90E  [IND4_DLW21H_90X60_SMD_1-4]  48.24 141.61 90 bottom
L22  90E  [IND4_DLW21H_90X60_SMD_1-4]  55.87 138.77 0 bottom
L23  10uH  [IND_MLZ2012N_90X60_SMD]  67.95 99.99 270 bottom
L24  90E  [IND4_DLW21H_90X60_SMD_1-4]  55.87 117.18 0 bottom
L25  2.2uH  [IND_74437368022_410X410_SMD_4]  30.27 25.28 90 bottom
L28  1uH  [IND_74438357010_170X170_SMD_3-1]  12.42 24.54 180 bottom
L29  0.47uH  [IND_744040640047_250X250_SMD_4-5]  29.26 96.47 180 bottom
L30  6.8uH  [IND_XAL1010_460X410_SMD]  60.38 12.35 90 bottom
NOREF  -  []  -3.02 -71.04 0 top
NOREF#2  -  []  83.16 0 90 top
NOREF#3  -  [unnamed#2]  78.08 185.42 0 top
NOREF#4  -  [unnamed#2]  2.29 9.68 0 top
NOREF#5  -  [unnamed#2]  36.38 176.5 0 top
NOREF#6  -  [unnamed#2]  5.08 5.08 0 top
NOREF#7  -  [unnamed#2]  40.66 45.7 0 top
NOREF#8  -  [unnamed#2]  78.11 9.68 0 top
NOREF#9  -  []  70.81 10.93 0 top
NOREF#10  -  [unnamed#2]  2.29 184.61 0 top
NOREF#11  -  [unnamed#2]  10.16 185.42 0 top
NOREF#12  -  []  -433.42 -123.59 0 top
NOREF#13  -  []  -431.9 -44.82 0 top
NOREF#14  -  []  601.78 104.8 0 top
NOREF#15  -  []  0 190.5 0 top
NOREF#16  -  [unnamed#2]  78.08 5.08 0 top
NOREF#17  -  []  -51.66 7.5 0 top
NOREF#18  -  [unnamed#2]  58.66 186.18 180 bottom
NOREF#19  -  [unnamed#2]  78.11 9.68 180 bottom
NOREF#20  -  [unnamed#2]  2.29 9.68 180 bottom
NOREF#21  -  [unnamed#2]  2.29 184.61 180 bottom
NOREF#22  -  [unnamed#2]  20.84 186.18 180 bottom
R1  49.9E_1%  [RES0402_0-5]  10.43 173.49 0 top
R2  49.9E_1%  [RES0402_0-5]  71.9 153.92 180 top
R3  49.9E_1%  [RES0402_0-5]  64.28 165.71 270 top
R4  0E  [RES0603_0-5]  66.03 167.59 90 top
R5  4.02K_1%  [RES0603_0-5]  8.93 167.73 90 top
R6  4.02K_1%  [RES0603_0-5]  70.55 158.5 180 top
R7  49.9E_1%  [RES0402_0-5]  10.43 151.39 0 top
R8  49.9E_1%  [RES0402_0-5]  71.9 134.36 180 top
R9  49.9E_1%  [RES0402_0-5]  64.28 145.39 270 top
R10  0E  [RES0603_0-5]  66.03 147.14 90 top
R11  4.02K_1%  [RES0603_0-5]  8.93 145.63 90 top
R12  4.02K_1%  [RES0603_0-5]  70.55 138.95 180 top
R13  10K_1%  [RES0402_0-5]  32.27 127.4 180 top
R14  0E  [RES0603_0-5]  69.92 118.97 270 bottom
R15  10K_1%  [RES0402_0-5]  24.52 124.06 0 top
R16  10K_1%  [RES0402_0-5]  24.77 125.72 90 top
R17  4.7K  [RES0402_0-5]  25.41 122.62 180 top
R18  49.9E_1%  [RES0402_0-5]  10.43 129.29 0 top
R19  49.9E_1%  [RES0402_0-5]  71.9 114.8 180 top
R20  49.9E_1%  [RES0402_0-5]  65.94 117.19 270 bottom
R21  49.9E_1%  [RES0402_0-5]  64.28 123.67 270 top
R22  10K_1%  [RES0402_0-5]  27.13 118.09 270 top
R23  0E  [RES0603_0-5]  66.03 125.42 90 top
R24  4.02K_1%  [RES0603_0-5]  8.93 123.53 90 top
R25  4.02K_1%  [RES0603_0-5]  70.55 119.39 180 top
R26  49.9E_1%  [RES0402_0-5]  10.43 107.19 0 top
R27  49.9E_1%  [RES0402_0-5]  71.9 95.24 180 top
R28  49.9E_1%  [RES0402_0-5]  64.28 102.46 270 top
R29  0E  [RES0603_0-5]  66.03 104.34 90 top
R30  4.02K_1%  [RES0603_0-5]  8.93 101.43 90 top
R31  4.02K_1%  [RES0603_0-5]  70.55 99.83 180 top
R32  4.02K_1%  [RES0603_0-5]  64.76 80.35 0 top
R33  49.9E_1%  [RES0402_0-5]  71.9 75.69 180 top
R34  10K_1%  [RES0402_0-5]  52.32 73.3 90 top
R35  10K_1%  [RES0402_0-5]  53.88 73.3 90 top
R36  10K_1%  [RES0402_0-5]  43.74 68.53 0 top
R37  10K_1%  [RES0402_0-5]  52.35 71.14 90 top
R38  10K_1%  [RES0402_0-5]  53.89 71.24 90 top
R39  23.2K_1%  [RES0402_0-5]  13.71 61.07 270 top
R40  4.02K_1%  [RES0603_0-5]  64.4 60.97 0 top
R41  10K_1%  [RES0402_0-5]  18.36 61.5 180 top
R42  40.2K_1%  [RES0402_0-5]  16.72 61.14 270 top
R43  10K_1%  [RES0402_0-5]  10.77 58.36 0 top
R44  49.9E_1%  [RES0402_0-5]  71.9 56.2 180 top
R45  4.02K_1%  [RES0603_0-5]  72 44.93 0 top
R46  10K_1%  [RES0402_0-5]  52.32 41.58 270 top
R47  10K_1%  [RES0402_0-5]  53.59 41.58 270 top
R48  49.9E_1%  [RES0402_0-5]  71.9 36.57 180 top
R49  4.02K_1%  [RES0603_0-5]  72 25.37 0 top
R50  49.9E_1%  [RES0402_0-5]  71.9 17.01 180 top
R51  0E  [RES0603_0-5]  69.92 158.6 270 bottom
R52  49.9E_1%  [RES0402_0-5]  65.94 156.81 270 bottom
R57  100K  [RES0402_0-5]  5.82 165.97 180 bottom
R61  16.9K_1%  [RES0402_0-5]  2.38 164.06 180 bottom
R62  30.9K_1%  [RES0402_0-5]  80.7 167.51 0 bottom
R63  69.8K_1%  [RES0402_0-5]  78.7 167.51 0 bottom
R64  309K_1%  [RES0402_0-5]  76.51 167.51 0 bottom
R65  44.2K_1%  [RES0402_0-5]  80.7 166.3 0 bottom
R66  150K  [RES0402_0-5]  2.38 161.2 180 bottom
R67  309K_1%  [RES0402_0-5]  6.57 159.99 180 bottom
R68  69.8K_1%  [RES0402_0-5]  4.38 159.99 180 bottom
R69  30.9K_1%  [RES0402_0-5]  2.38 159.99 180 bottom
R70  16.9K_1%  [RES0402_0-5]  80.7 163.44 0 bottom
R71  100K  [RES0402_0-5]  77.26 161.53 0 bottom
R72  0E  [RES0603_0-5]  69.92 139.04 270 bottom
R73  49.9E_1%  [RES0402_0-5]  65.94 137.25 270 bottom
R78  100K  [RES0402_0-5]  5.82 142.5 180 bottom
R81  16.9K_1%  [RES0402_0-5]  2.38 140.59 180 bottom
R82  100E_1%  [RES0402_0-5]  19.91 126.64 90 bottom
R83  30.9K_1%  [RES0402_0-5]  80.7 147.88 0 bottom
R84  69.8K_1%  [RES0402_0-5]  78.7 147.88 0 bottom
R85  309K_1%  [RES0402_0-5]  76.51 147.88 0 bottom
R86  4.7K  [RES0402_0-5]  39.51 127.33 90 bottom
R87  4.7K  [RES0402_0-5]  38.24 127.33 90 bottom
R88  10K_1%  [RES0402_0-5]  31.83 127.94 90 bottom
R89  44.2K_1%  [RES0402_0-5]  80.7 146.67 0 bottom
R90  150K  [RES0402_0-5]  2.38 137.73 180 bottom
R91  309K_1%  [RES0402_0-5]  6.57 136.52 180 bottom
R92  69.8K_1%  [RES0402_0-5]  4.38 136.52 180 bottom
R93  30.9K_1%  [RES0402_0-5]  2.38 136.52 180 bottom
R94  100E_1%  [RES0402_0-5]  41.77 124.83 90 bottom
R95  16.9K_1%  [RES0402_0-5]  80.7 143.8 0 bottom
R96  100E_1%  [RES0402_0-5]  19.73 123.23 90 bottom
R97  100K  [RES0402_0-5]  77.26 141.9 0 bottom
R98  100E_1%  [RES0402_0-5]  41.57 121.9 90 bottom
R99  4.7K  [RES0402_0-5]  39.21 117.19 0 bottom
R102  100K  [RES0402_0-5]  5.82 121.57 180 bottom
R106  16.9K_1%  [RES0402_0-5]  2.38 119.66 180 bottom
R108  30.9K_1%  [RES0402_0-5]  80.7 127.84 0 bottom
R109  69.8K_1%  [RES0402_0-5]  78.7 127.84 0 bottom
R110  309K_1%  [RES0402_0-5]  76.51 127.84 0 bottom
R111  44.2K_1%  [RES0402_0-5]  80.7 126.63 0 bottom
R112  150K  [RES0402_0-5]  2.38 116.82 180 bottom
R113  309K_1%  [RES0402_0-5]  6.57 115.59 180 bottom
R114  69.8K_1%  [RES0402_0-5]  4.38 115.59 180 bottom
R115  30.9K_1%  [RES0402_0-5]  2.38 115.59 180 bottom
R116  16.9K_1%  [RES0402_0-5]  80.7 123.76 0 bottom
R117  0E  [RES0603_0-5]  69.92 99.92 270 bottom
R118  100K  [RES0402_0-5]  77.26 121.86 0 bottom
R119  49.9E_1%  [RES0402_0-5]  65.94 98.14 270 bottom
R121  100K  [RES0402_0-5]  5.82 99.9 180 bottom
R122  69.8K_1%  [RES0402_0-5]  78.19 108.29 0 bottom
R123  309K_1%  [RES0402_0-5]  76.13 108.29 0 bottom
R125  30.9K_1%  [RES0402_0-5]  80.57 108.17 0 bottom
R128  16.9K_1%  [RES0402_0-5]  2.38 98 180 bottom
R129  44.2K_1%  [RES0402_0-5]  80.57 106.95 0 bottom
R130  30.9K_1%  [RES0402_0-5]  80.7 88.98 0 bottom
R131  69.8K_1%  [RES0402_0-5]  78.7 88.98 0 bottom
R132  309K_1%  [RES0402_0-5]  76.51 88.98 0 bottom
R135  150K  [RES0402_0-5]  80.7 87.77 0 bottom
R136  150K  [RES0402_0-5]  2.38 95.14 180 bottom
R137  16.9K_1%  [RES0402_0-5]  80.57 104.09 0 bottom
R138  309K_1%  [RES0402_0-5]  6.57 93.92 180 bottom
R139  69.8K_1%  [RES0402_0-5]  4.38 93.92 180 bottom
R140  30.9K_1%  [RES0402_0-5]  2.38 93.92 180 bottom
R141  16.9K_1%  [RES0402_0-5]  80.7 84.9 0 bottom
R144  100K  [RES0402_0-5]  77.26 102.31 0 bottom
R145  0E  [RES0402_0-5]  32.55 87.71 0 bottom
R146  10K_1%  [RES0402_0-5]  14.16 92.96 270 bottom
R147  10K_1%  [RES0402_0-5]  12.86 92.96 90 bottom
R148  10K_1%  [RES0402_0-5]  11.59 92.96 90 bottom
R149  10K_1%  [RES0402_0-5]  10.3 92.96 270 bottom
R150  100K  [RES0402_0-5]  77.26 83 0 bottom
R151  10K_1%  [RES0402_0-5]  8.4 90.54 0 bottom
R152  10K_1%  [RES0402_0-5]  8.4 89.23 180 bottom
R153  10K_1%  [RES0402_0-5]  12.08 83.83 180 bottom
R154  10E_1%  [RES0402_0-5]  18.57 81.91 90 bottom
R155  10E_1%  [RES0402_0-5]  17.47 81.91 90 bottom
R156  10E_1%  [RES0402_0-5]  14.28 81.16 90 bottom
R157  4.7K  [RES0402_0-5]  21.17 78.21 90 bottom
R158  10K_1%  [RES0402_0-5]  7.18 77.74 90 bottom
R159  22E_1%  [RES0402_0-5]  12.71 77.21 0 bottom
R160  100E_1%  [RES0402_0-5]  49.97 76.39 0 bottom
R161  100E_1%  [RES0402_0-5]  46.03 76.39 0 bottom
R162  30.9K_1%  [RES0402_0-5]  80.7 69.67 0 bottom
R163  69.8K_1%  [RES0402_0-5]  78.7 69.67 0 bottom
R164  309K_1%  [RES0402_0-5]  76.51 69.67 0 bottom
R165  22E_1%  [RES0402_0-5]  13.2 76.72 90 bottom
R166  150K  [RES0402_0-5]  80.7 68.47 0 bottom
R167  4.7K  [RES0402_0-5]  20.96 74.16 270 bottom
R168  16.9K_1%  [RES0402_0-5]  80.7 65.6 0 bottom
R169  100K  [RES0402_0-5]  77.26 63.69 0 bottom
R170  4.7K  [RES0402_0-5]  20.91 68.17 90 bottom
R171  88.7K_1%  [RES0402_0-5]  12.06 61.39 0 top
R172  4.7K  [RES0402_0-5]  22.1 68.15 90 bottom
R173  100E_1%  [RES0402_0-5]  23.83 67.17 180 bottom
R174  100E_1%  [RES0402_0-5]  6.37 66.4 0 bottom
R175  100E_1%  [RES0402_0-5]  27.14 62.71 90 bottom
R176  4.7K  [RES0402_0-5]  49.94 57.99 0 bottom
R177  100E_1%  [RES0402_0-5]  3.63 57.54 180 bottom
R178  4.7K  [RES0402_0-5]  23.15 57.24 0 bottom
R179  4.7K  [RES0402_0-5]  49.94 56.83 0 bottom
R180  4.7K  [RES0402_0-5]  41.13 56.27 270 bottom
R181  30.9K_1%  [RES0402_0-5]  80.7 50.23 0 bottom
R182  69.8K_1%  [RES0402_0-5]  78.7 50.23 0 bottom
R183  309K_1%  [RES0402_0-5]  76.51 50.23 0 bottom
R184  150K  [RES0402_0-5]  80.7 49.02 0 bottom
R185  100E_1%  [RES0402_0-5]  52.32 51.88 0 bottom
R186  100E_1%  [RES0402_0-5]  46.81 51.88 0 bottom
R187  16.9K_1%  [RES0402_0-5]  80.7 46.15 0 bottom
R188  100K  [RES0402_0-5]  77.26 44.24 0 bottom
R189  30.9K_1%  [RES0402_0-5]  80.7 31.37 0 bottom
R190  69.8K_1%  [RES0402_0-5]  78.7 31.37 0 bottom
R191  309K_1%  [RES0402_0-5]  76.51 31.37 0 bottom
R192  150K  [RES0402_0-5]  80.7 30.16 0 bottom
R193  53.6K_1%  [RES0402_0-5]  41.67 24.52 0 bottom
R194  16.9K_1%  [RES0402_0-5]  80.7 27.29 0 bottom
R195  100K  [RES0402_0-5]  77.26 25.39 0 bottom
R196  2.49K_1%  [RES0402_0-5]  37.64 16.6 270 bottom
R197  0E  [RES0402_0-5]  18.26 24.31 180 top
R198  10K_1%  [RES0402_0-5]  41.55 17.26 0 bottom
R199  30.9K_1%  [RES0402_0-5]  41.55 18.44 180 bottom
R200  1K_1%  [RES0402_0-5]  24.1 60.05 270 bottom
R201  1K_1%  [RES0402_0-5]  25.14 60.04 270 bottom
R202  1K_1%  [RES0402_0-5]  43.99 54.52 180 bottom
R203  1K_1%  [RES0402_0-5]  43.99 53.2 180 bottom
R204  1K_1%  [RES0402_0-5]  41.51 119.44 270 bottom
R205  1K_1%  [RES0402_0-5]  42.5 119.44 270 bottom
R206  0E  [RES0402_0-5]  46.78 105.34 270 top
R207  4.99K_1%  [RES0402_0-5]  45.76 109.68 90 top
R208  1.87K_1%  [RES0402_0-5]  44.36 109.68 90 top
R209  0E  [RES0402_0-5]  26.74 30.56 270 top
R210  4.99K_1%  [RES0402_0-5]  24.63 34.42 90 top
R211  1.87K_1%  [RES0402_0-5]  23.2 34.46 90 top
R212  0E  [RES0402_0-5]  16.17 31.73 270 top
R213  4.99K_1%  [RES0402_0-5]  13.96 35.82 90 top
R214  1.87K_1%  [RES0402_0-5]  12.56 35.82 90 top
R222  49.9E_1%  [RES0402_0-5]  73.78 175.36 270 top
R223  10K_1%  [RES0402_0-5]  34.25 169.63 180 bottom
R228  10K_1%  [RES0402_0-5]  30.81 160.72 90 bottom
R230  10E_1%  [RES0402_0-5]  19.88 78.13 0 top
R232  40.2K_1%  [RES0402_0-5]  32.8 160.62 270 top
R233  4.87K_1%  [RES0402_0-5]  30.8 160.72 270 top
R234  10K_1%  [RES0402_0-5]  32.8 160.73 90 bottom
R236  0E  [RES0402_0-5]  31.81 160.72 90 bottom
R239  10K_1%  [RES0402_0-5]  18.69 20.02 0 bottom
R241  174K_1%  [RES0402_0-5]  14.25 18.87 270 bottom
R243  3.83K_1%  [RES0402_0-5]  18.69 18.8 180 bottom
R244  6.49K_1%  [RES0402_0-5]  16.75 19.56 270 bottom
R245  44.2K_1%  [RES0402_0-5]  17.59 26.05 0 top
R253  102K_1%  [RES0402_0-5]  34.37 17.15 90 bottom
R254  36.5K_1%  [RES0402_0-5]  35.37 17.15 270 bottom
R255  0.01E_1%  [RES1206_0-75]  49.55 2.12 0 bottom
R256  4.12K_1%  [RES0402_0-5]  49.06 9.43 90 top
R257  365K_1%  [RES0402_0-5]  50.06 9.43 270 top
R258  10K_1%  [RES0201_0-5]  53.51 5.96 180 top
R259  866E_1%  [RES0402_0-5]  51.74 5.96 180 top
TP1  THRU HOLE  [TP_40X65]  24.13 96.16 270 bottom
TP2  THRU HOLE  [TP_40X65]  2.59 157.35 0 bottom
TP3  -  [TP40_SMD]  18.23 127.66 90 bottom
TP4  -  [TP40_SMD]  18.23 125.5 90 bottom
TP5  -  [TP40_SMD]  44.27 127.14 270 bottom
TP6  -  [TP40_SMD]  44.27 125.06 270 bottom
TP7  -  [TP40_SMD]  44.26 122.84 180 bottom
TP8  -  [TP40_SMD]  44.31 120.63 180 bottom
TP9  -  [TP40_SMD]  14.55 123.91 180 bottom
TP10  -  [TP40_SMD]  14.55 126.04 180 bottom
TP11  -  [TP40_SMD]  42.58 116.74 90 bottom
TP12  THRU HOLE  [TP_40X65]  43.48 94.02 180 bottom
TP13  -  [TP40_SMD]  47.39 82.56 270 bottom
TP14  -  [TP40_SMD]  44.67 82.56 270 bottom
TP15  -  [TP40_SMD]  51.33 79.23 270 bottom
TP16  -  [TP40_SMD]  48.61 79.23 270 bottom
TP17  -  [TP40_SMD]  25.15 71.05 0 bottom
TP18  -  [TP40_SMD]  22.76 71.05 0 bottom
TP19  -  [TP40_SMD]  7.45 68.31 0 bottom
TP20  -  [TP40_SMD]  5.29 68.31 0 bottom
TP21  -  [TP40_SMD]  29.34 58.35 0 bottom
TP22  -  [TP40_SMD]  27.18 58.35 0 bottom
TP23  -  [TP40_SMD]  25.59 55.94 90 bottom
TP24  -  [TP40_SMD]  4.71 55.48 0 bottom
TP25  -  [TP40_SMD]  2.55 55.48 0 bottom
TP26  -  [TP40_SMD]  40.72 52.17 90 bottom
TP27  -  [TP40_SMD]  53.6 49.9 180 bottom
TP28  -  [TP40_SMD]  51.05 49.9 0 bottom
TP29  -  [TP40_SMD]  48.09 49.9 180 bottom
TP30  -  [TP40_SMD]  45.54 49.9 0 bottom
TP31  THRU HOLE  [TP_40X65]  3.81 24.64 270 bottom
TP32  -  [TP40_SMD]  38.4 24.98 180 bottom
TP33  THRU HOLE  [TP_40X65]  7.85 24.65 90 bottom
TP34  THRU HOLE  [TP_40X65]  39.16 2.43 180 top
TP35  -  [TP40_SMD]  24.54 11.3 0 bottom
TP36  5002  [TP_CIR67D40_TH_4-6]  7.22 10.71 0 bottom
TP37  -  [TP40_SMD]  66.79 10.99 180 top
TP38  -  [TP30_SMD]  45.48 103.95 270 bottom
TP39  -  [TP30_SMD]  20.75 35.94 270 bottom
TP40  -  [TP30_SMD]  3.73 28.24 180 bottom
TP41  -  [TP40_SMD]  33.63 158.57 270 bottom
TP42  -  [TP40_SMD]  38.47 158.57 270 bottom
TP43  -  [TP40_SMD]  36.09 158.57 270 bottom
TP44  -  [TP40_SMD]  25.65 166.34 180 bottom
TP45  -  [TP40_SMD]  25.65 168.63 180 bottom
TP50  -  [TP40_SMD]  15.92 72.82 180 bottom
TP51  -  [TP40_SMD]  43.15 109.86 270 bottom
TP52  -  [TP40_SMD]  33.2 54.13 270 bottom
TP53  -  [TP40_SMD]  5.33 40.79 180 bottom
TP55  -  [TP40_SMD]  27.61 34.14 180 bottom
TP56  -  [TP40_SMD]  76.22 31.58 90 top
U1  TPD2E001DRLR  [SOT553-5_0-6]  48.49 166.37 270 bottom
U3  TPS25940ARVC  [QFN20_19-68_120X160_0-8]  6.11 162.8 270 bottom
U4  TPS25940ARVC  [QFN20_19-68_120X160_0-8]  76.97 164.7 90 bottom
U5  TPD2E001DRLR  [SOT553-5_0-6]  48.49 144.78 90 bottom
U7  TPS25940ARVC  [QFN20_19-68_120X160_0-8]  6.11 139.33 270 bottom
U8  TPS25940ARVC  [QFN20_19-68_120X160_0-8]  76.97 145.07 90 bottom
U9  DS90UB9702TRURRQ1  [QFN88_19-68_480X480_0-9_EP6-8]  31.07 117.41 180 bottom
U10  TPD2E001DRLR  [SOT553-5_0-6]  59.58 135.35 270 bottom
U12  TPS25940ARVC  [QFN20_19-68_120X160_0-8]  6.11 118.4 270 bottom
U13  TPS25940ARVC  [QFN20_19-68_120X160_0-8]  76.97 125.03 90 bottom
U14  TPD2E001DRLR  [SOT553-5_0-6]  59.58 113.76 270 bottom
U16  TPS25940ARVC  [QFN20_19-68_120X160_0-8]  6.11 96.73 270 bottom
U17  TPS25940ARVC  [QFN20_19-68_120X160_0-8]  76.97 105.48 90 bottom
U18  TPS25940ARVC  [QFN20_19-68_120X160_0-8]  76.97 86.17 90 bottom
U19  TPS6282618DMQT  [VSONHR6_TPS62826_60X60_1]  31.56 89.68 90 bottom
U20  CAT24C256WI-GT3  [SOIC8_1-8]  12.23 88.14 270 bottom
U21  25MHz  [OSC4_ASDMB_100X85_SMD]  9.91 77.99 0 bottom
U22  LMK00105SQ  [WQFN24_19-68_160X160]  17.46 77.52 90 bottom
U23  TPS25940ARVC  [QFN20_19-68_120X160_0-8]  76.97 66.86 90 bottom
U24  DS90UB9702TRURRQ1  [QFN88_19-68_480X480_0-9_EP6-8]  41.08 64.32 90 bottom
U25  DS90UB9702TRURRQ1  [QFN88_19-68_480X480_0-9_EP6-8]  15.1 57.19 180 bottom
U26  TPS25940ARVC  [QFN20_19-68_120X160_0-8]  76.97 47.41 90 bottom
U27  TPS25940ARVC  [QFN20_19-68_120X160_0-8]  76.97 28.56 90 bottom
U28  TPS54620RHLR  [QFN14_19-68_145X145]  39.67 21.36 270 bottom
U29  TPS74801TDRCRQ1  [VSON10_TPS74801-Q1_120X120_1]  44.2 106.25 90 top
U30  TPS74801TDRCRQ1  [VSON10_TPS74801-Q1_120X120_1]  24.23 31.34 90 top
U31  TPS74801TDRCRQ1  [VSON10_TPS74801-Q1_120X120_1]  13.67 32.51 90 top
U32  PDS90UB971BARHBTQ1  [QFN32_19-68_200X200_1_EP3-8]  31.93 165.56 270 bottom
U33  TPS54618RTER  [QFN16_19-68_120X120_0-8_EP1-8]  17 22.79 180 bottom
U35  LM25085ASD  [DFN8_19-68_120X120_0-8_EP1-7X2-1]  49.55 5.6 270 bottom
U36  SI7149DP  [POWERPAKSO8_SI7848BDP_240X200_1-2]  57.71 4.11 180 bottom

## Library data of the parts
C1-C3 C5-C14 C16-C25 C27-C34 C36-C41 C43-C47 C49-C52 C54 C55 C57-C79 C81-C87 C89 C91-C99 C101-C104 C106-C123 C125 C126 C132 C133 C135 C136 C139-C149 C151 C152 C154 C156 C160 C161 C163 C164 C166 C167 C170-C187 C189-C191 C195 C196 C198 C201 C203-C210 C213-C216 C218 C219 C223 C225 C226 C228 C230 C231 C233-C236 C238-C249 C251-C258 C260-C313 C316-C319 C321-C336 C338 C339 C341-C348 C350-C374 C381-C387 C390 C392 C398-C400 C405-C474 C484 C485 C491-C493 C495 C496 C500-C502 C507-C519 C521-C524 C526 C527 = CAP
C137 C138 C168 C169 C211 C212 C224 C229 C232 C250 C314 C340 C525 C528 C529 = CAP_POL
D1 = DIODE_V20PW45C
D2 = DIODE_TVS
D3 = DIODE_SCHOTTKY_SS3P4L
F1 F2 = FUSE_HOLDER_0154
FL1-FL71 FL76 FL78 FL80 = EMIFILTER_IND
J1 J2 J20 = CON_20X2_QTH-020-DP
J3 J6 J9 J12 = CON_JACK4_EXG.0B.304
J4 J5 J7 J8 J10 J11 J13-J18 J21 = CON5_MCXJACK_TH
J19 = CON_TRBLK_2X1
